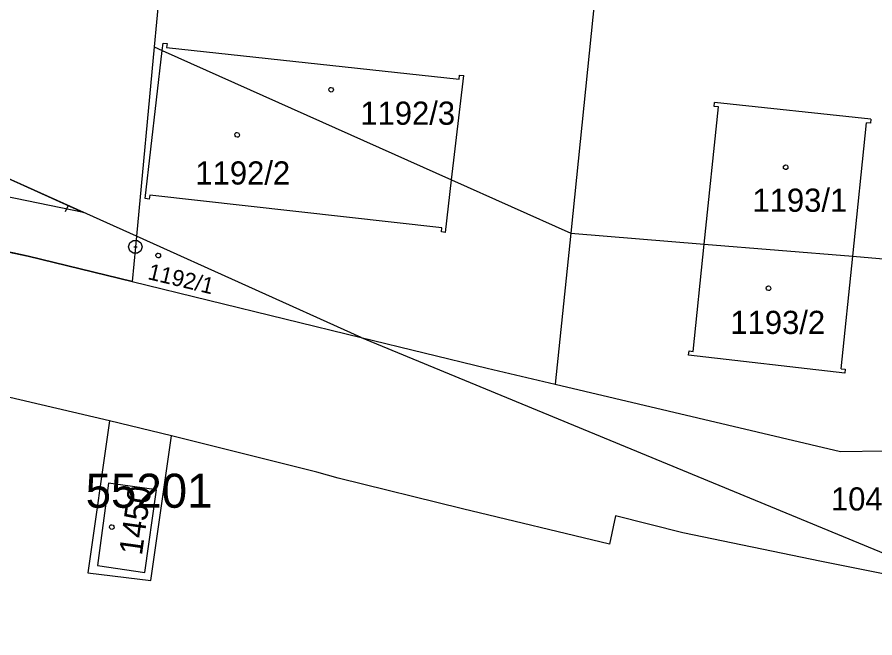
# Model space of a CAD drawing. Extents: x -777309 to -774195, y -1144706 to -1143600.
# Drawn here: x -775252.8 to -775189.8, y -1144374.9 to -1144329.3 of the extents above; entities that cross this region are included whole.
import ezdxf

# ---------------------------------------------------------------- set-up
doc = ezdxf.new("R2010")
doc.units = 0
for name, color, linetype in [('1', 7, 'Continuous'), ('11', 7, 'Continuous'), ('12', 7, 'Continuous'), ('13', 7, 'Continuous'), ('2', 7, 'Continuous'), ('4', 7, 'Continuous'), ('5', 7, 'Continuous'), ('8', 7, 'Continuous')]:
    doc.layers.add(name, color=color, linetype=linetype)

msp = doc.modelspace()

# ---------------------------------------------------------------- linework, layer by layer
at = {"layer": '1'}
for p, q in [((-775241.77, -1144321.45), (-775242.71, -1144331.45)), ((-775210.05, -1144324.7), (-775212.14, -1144345.14)), ((-775242.71, -1144331.45), (-775244.01, -1144345.37)), ((-775242.71, -1144331.45), (-775242.11, -1144331.72)), ((-775242.11, -1144331.72), (-775220.88, -1144341.23)), ((-775244.01, -1144345.37), (-775261.93, -1144337.3)), ((-775220.88, -1144341.23), (-775212.14, -1144345.14)), ((-775251.95, -1144346.82), (-775262.59, -1144344.6)), ((-775212.14, -1144345.14), (-775213.28, -1144356.23)), ((-775212.14, -1144345.14), (-775202.35, -1144345.94)), ((-775244.01, -1144345.37), (-775244.08, -1144346.15)), ((-775227.51, -1144352.79), (-775244.01, -1144345.37)), ((-775202.35, -1144345.94), (-775191.45, -1144346.84)), ((-775244.08, -1144346.15), (-775244.32, -1144348.69)), ((-775244.32, -1144348.69), (-775251.95, -1144346.82)), ((-775191.45, -1144346.84), (-775185.12, -1144347.36)), ((-775244.32, -1144348.69), (-775227.51, -1144352.79)), ((-775227.51, -1144352.79), (-775182.38, -1144371.44)), ((-775227.51, -1144352.79), (-775218.28, -1144355.05)), ((-775218.28, -1144355.05), (-775213.28, -1144356.23)), ((-775213.28, -1144356.23), (-775192.34, -1144361.18)), ((-775245.99, -1144358.92), (-775253.71, -1144357.11)), ((-775245.99, -1144358.92), (-775247.57, -1144370.08)), ((-775241.44, -1144360.01), (-775245.99, -1144358.92)), ((-775242.95, -1144370.63), (-775241.44, -1144360.01)), ((-775230.77, -1144362.69), (-775241.44, -1144360.01)), ((-775192.34, -1144361.18), (-775189.15, -1144361.13)), ((-775229.2, -1144363.12), (-775230.77, -1144362.69)), ((-775220.08, -1144365.37), (-775229.2, -1144363.12)), ((-775209.29, -1144367.97), (-775220.08, -1144365.37)), ((-775208.86, -1144365.9), (-775209.29, -1144367.97)), ((-775203.92, -1144367.13), (-775208.86, -1144365.9)), ((-775193.75, -1144369.24), (-775203.92, -1144367.13)), ((-775184.75, -1144371.03), (-775193.75, -1144369.24)), ((-775247.57, -1144370.08), (-775242.95, -1144370.63))]:
    msp.add_line(p, q, dxfattribs=at)
at = {"layer": '11'}
msp.add_lwpolyline([(-775308.24, -1144339.37), (-775297.97, -1144340.23), (-775277.83, -1144342.65), (-775262.59, -1144344.6), (-775251.95, -1144346.82), (-775244.32, -1144348.69), (-775227.51, -1144352.79), (-775218.28, -1144355.05), (-775213.28, -1144356.23), (-775192.34, -1144361.18), (-775189.15, -1144361.13), (-775180.09, -1144362.23), (-775180.7, -1144372.14), (-775179.02, -1144372.13), (-775201.2, -1144431.58), (-775249.17, -1144413.49)], dxfattribs=at)
msp.add_lwpolyline([(-775242.95, -1144370.63), (-775241.44, -1144360.01), (-775245.99, -1144358.92), (-775247.57, -1144370.08)], close=True, dxfattribs=at)
at = {"layer": '12'}
for p, q in [((-775242.11, -1144331.72), (-775242.05, -1144331.19)), ((-775242.05, -1144331.19), (-775241.75, -1144331.22)), ((-775241.75, -1144331.22), (-775241.79, -1144331.52)), ((-775243.36, -1144342.6), (-775242.11, -1144331.72)), ((-775241.79, -1144331.52), (-775220.32, -1144333.83)), ((-775220.88, -1144341.23), (-775219.99, -1144333.56)), ((-775220.32, -1144333.83), (-775220.29, -1144333.53)), ((-775220.29, -1144333.53), (-775219.99, -1144333.56)), ((-775202.35, -1144345.94), (-775201.31, -1144335.87)), ((-775201.61, -1144335.84), (-775201.58, -1144335.54)), ((-775201.31, -1144335.87), (-775201.61, -1144335.84)), ((-775190.11, -1144336.77), (-775201.58, -1144335.54)), ((-775191.45, -1144346.84), (-775190.44, -1144337.04)), ((-775190.14, -1144337.07), (-775190.44, -1144337.04)), ((-775190.11, -1144336.77), (-775190.14, -1144337.07)), ((-775221.32, -1144345.09), (-775220.88, -1144341.23)), ((-775243.06, -1144342.64), (-775243.36, -1144342.6)), ((-775243.02, -1144342.34), (-775243.06, -1144342.64)), ((-775221.59, -1144344.75), (-775243.02, -1144342.34)), ((-775221.62, -1144345.05), (-775221.59, -1144344.75)), ((-775221.32, -1144345.09), (-775221.62, -1144345.05)), ((-775244.01, -1144345.37), (-775244.08, -1144346.15)), ((-775227.51, -1144352.79), (-775244.01, -1144345.37)), ((-775203.16, -1144353.83), (-775202.35, -1144345.94)), ((-775244.08, -1144346.15), (-775244.32, -1144348.69)), ((-775192.3, -1144355.09), (-775191.45, -1144346.84)), ((-775244.32, -1144348.69), (-775227.51, -1144352.79)), ((-775203.49, -1144354.09), (-775203.46, -1144353.79)), ((-775192.03, -1144355.42), (-775203.49, -1144354.09)), ((-775203.46, -1144353.79), (-775203.16, -1144353.83)), ((-775192.3, -1144355.09), (-775192, -1144355.12)), ((-775192, -1144355.12), (-775192.03, -1144355.42)), ((-775246.06, -1144363.49), (-775246.87, -1144369.55)), ((-775242.54, -1144363.98), (-775246.06, -1144363.49)), ((-775243.39, -1144370.04), (-775242.54, -1144363.98)), ((-775246.87, -1144369.55), (-775243.39, -1144370.04))]:
    msp.add_line(p, q, dxfattribs=at)
at = {"layer": '13'}
msp.add_line((-775249.017, -1144343.118), (-775249.222, -1144343.574), dxfattribs=at)
msp.add_lwpolyline([(-775263.64, -1144336.63), (-775261.93, -1144337.3), (-775258.95, -1144338.64), (-775256.67, -1144339.67), (-775247.88, -1144343.63), (-775261.21, -1144340.89), (-775261.09, -1144339.21), (-775263.97, -1144338.69), (-775263.69, -1144337.11)], close=True, dxfattribs=at)
at = {"layer": '4'}
for p, q in [((-775242.11, -1144331.72), (-775242.05, -1144331.19)), ((-775242.05, -1144331.19), (-775241.75, -1144331.22)), ((-775241.75, -1144331.22), (-775241.79, -1144331.52)), ((-775243.36, -1144342.6), (-775242.11, -1144331.72)), ((-775241.79, -1144331.52), (-775220.32, -1144333.83)), ((-775220.88, -1144341.23), (-775219.99, -1144333.56)), ((-775220.32, -1144333.83), (-775220.29, -1144333.53)), ((-775220.29, -1144333.53), (-775219.99, -1144333.56)), ((-775202.35, -1144345.94), (-775201.31, -1144335.87)), ((-775201.61, -1144335.84), (-775201.58, -1144335.54)), ((-775201.31, -1144335.87), (-775201.61, -1144335.84)), ((-775190.11, -1144336.77), (-775201.58, -1144335.54)), ((-775191.45, -1144346.84), (-775190.44, -1144337.04)), ((-775190.14, -1144337.07), (-775190.44, -1144337.04)), ((-775190.11, -1144336.77), (-775190.14, -1144337.07)), ((-775221.32, -1144345.09), (-775220.88, -1144341.23)), ((-775243.06, -1144342.64), (-775243.36, -1144342.6)), ((-775243.02, -1144342.34), (-775243.06, -1144342.64)), ((-775221.59, -1144344.75), (-775243.02, -1144342.34)), ((-775221.62, -1144345.05), (-775221.59, -1144344.75)), ((-775221.32, -1144345.09), (-775221.62, -1144345.05)), ((-775203.16, -1144353.83), (-775202.35, -1144345.94)), ((-775192.3, -1144355.09), (-775191.45, -1144346.84)), ((-775203.49, -1144354.09), (-775203.46, -1144353.79)), ((-775192.03, -1144355.42), (-775203.49, -1144354.09)), ((-775203.46, -1144353.79), (-775203.16, -1144353.83)), ((-775192.3, -1144355.09), (-775192, -1144355.12)), ((-775192, -1144355.12), (-775192.03, -1144355.42)), ((-775246.06, -1144363.49), (-775246.87, -1144369.55)), ((-775242.54, -1144363.98), (-775246.06, -1144363.49)), ((-775243.39, -1144370.04), (-775242.54, -1144363.98)), ((-775246.87, -1144369.55), (-775243.39, -1144370.04))]:
    msp.add_line(p, q, dxfattribs=at)
at = {"layer": '5'}
for points in [[(-775229.72, -1144334.44), (-775229.62, -1144334.46), (-775229.57, -1144334.55), (-775229.55, -1144334.61), (-775229.57, -1144334.7), (-775229.65, -1144334.77), (-775229.72, -1144334.78), (-775229.81, -1144334.75), (-775229.87, -1144334.69), (-775229.89, -1144334.61), (-775229.87, -1144334.52), (-775229.79, -1144334.45)], [(-775236.62, -1144337.75), (-775236.52, -1144337.77), (-775236.47, -1144337.86), (-775236.45, -1144337.92), (-775236.47, -1144338.01), (-775236.55, -1144338.08), (-775236.62, -1144338.09), (-775236.71, -1144338.06), (-775236.77, -1144338), (-775236.79, -1144337.92), (-775236.77, -1144337.83), (-775236.69, -1144337.76)], [(-775196.37, -1144340.13), (-775196.27, -1144340.15), (-775196.22, -1144340.24), (-775196.2, -1144340.3), (-775196.22, -1144340.39), (-775196.3, -1144340.46), (-775196.37, -1144340.47), (-775196.46, -1144340.44), (-775196.52, -1144340.38), (-775196.54, -1144340.3), (-775196.52, -1144340.21), (-775196.44, -1144340.14)], [(-775242.4, -1144346.61), (-775242.3, -1144346.63), (-775242.25, -1144346.72), (-775242.23, -1144346.78), (-775242.25, -1144346.87), (-775242.33, -1144346.94), (-775242.4, -1144346.95), (-775242.49, -1144346.92), (-775242.55, -1144346.86), (-775242.57, -1144346.78), (-775242.55, -1144346.69), (-775242.47, -1144346.62)], [(-775197.63, -1144349.01), (-775197.53, -1144349.03), (-775197.48, -1144349.12), (-775197.46, -1144349.18), (-775197.48, -1144349.27), (-775197.56, -1144349.34), (-775197.63, -1144349.35), (-775197.72, -1144349.32), (-775197.78, -1144349.26), (-775197.8, -1144349.18), (-775197.78, -1144349.09), (-775197.7, -1144349.02)], [(-775245.8, -1144366.55), (-775245.7, -1144366.57), (-775245.65, -1144366.66), (-775245.63, -1144366.72), (-775245.65, -1144366.81), (-775245.73, -1144366.88), (-775245.8, -1144366.89), (-775245.89, -1144366.86), (-775245.95, -1144366.8), (-775245.97, -1144366.72), (-775245.95, -1144366.63), (-775245.87, -1144366.56)]]:
    msp.add_lwpolyline(points, close=True, dxfattribs=at)
at = {"layer": '8'}
msp.add_line((-775244.2, -1144346.15), (-775243.96, -1144346.15), dxfattribs=at)
msp.add_lwpolyline([(-775243.93, -1144345.67), (-775243.68, -1144345.85), (-775243.58, -1144346.14), (-775243.68, -1144346.43), (-775243.93, -1144346.61), (-775244.24, -1144346.61), (-775244.49, -1144346.43), (-775244.59, -1144346.14), (-775244.49, -1144345.85), (-775244.24, -1144345.67)], close=True, dxfattribs=at)

# ---------------------------------------------------------------- texts
at = {"layer": '11'}
msp.add_text('55201', height=2.5, dxfattribs=at).set_placement((-775247.725, -1144365.3))
at = {"layer": '2'}
for s, p in [('1192/3', (-775227.577, -1144337.18)), ('1192/2', (-775239.677, -1144341.57)), ('1193/1', (-775198.807, -1144343.57)), ('1193/2', (-775200.427, -1144352.54)), ('1042/27', (-775193.047, -1144365.5))]:
    msp.add_text(s, height=1.7, dxfattribs=at).set_placement(p)
for s, height, rotation, p in [('1192/1', 1.19, 346.58217, (-775243.233, -1144348.504)), ('1450', 1.7, 81.99026, (-775243.605, -1144368.841))]:
    msp.add_text(s, height=height, rotation=rotation, dxfattribs=at).set_placement(p)

doc.saveas('drawing.dxf')
